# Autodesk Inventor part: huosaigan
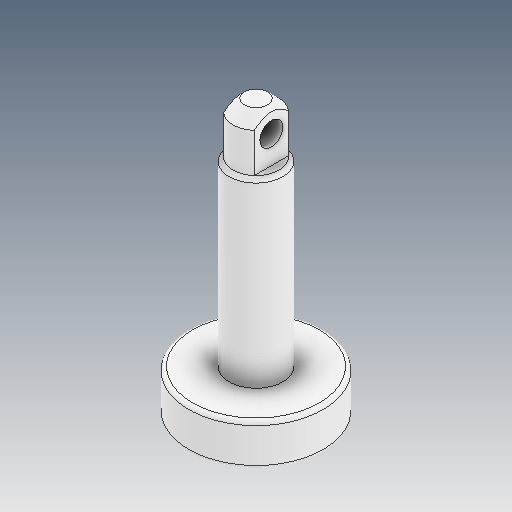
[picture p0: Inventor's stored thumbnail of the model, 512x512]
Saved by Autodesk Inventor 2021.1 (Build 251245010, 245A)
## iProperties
Created: 2021-06
Part Number: huosaigan
Material: Ogólny
Document SubType Name: Modeling
Designer: user
Density: 1 g/cm^3
Appearance: Domyślna
Author: user
Revision Number: ÈÎºÎ
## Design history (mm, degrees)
feature "ÇÐ³ý-À­Éì2"
node "Bryła1"
